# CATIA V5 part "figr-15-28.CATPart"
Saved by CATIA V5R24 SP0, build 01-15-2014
Part number: Part1
Bounding box of the stored display mesh (mm): x -61.282 to 61.282, y -26.72 to 26.72, z 0 to 45.75
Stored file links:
  D:\KAVITA\CATIA V5-6R2014 Project_ Kavita\CATIA V5-6R2014_partfiles\Partfiles\c15_catia_v5-6r2014_prt\figr-15-28.CATPart
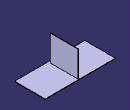
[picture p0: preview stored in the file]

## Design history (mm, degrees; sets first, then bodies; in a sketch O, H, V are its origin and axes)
SheetMetalParameters1: Thickness 0.75, BendRadius 1, KFactor 0.356492 {= log(min(100,max(20*SheetMetalParameters1.BendRadius,SheetMetalParameters1.Thickness)/SheetMetalParameters1.Thickness))/log(100)/2}, ReliefRadialLength 1, ReliefAxialLength 2, MinimumBendRadius 0
Body1 (main body)
  Sketch1 on xy-plane, origin (0, 0, 0), H (1, 0, 0), V (0, 1, 0)
    line L1 (61.282, 26.7197) -> (61.282, -26.7197)
    line L2 (61.282, -26.7197) -> (-61.282, -26.7197)
    line L3 (-61.282, -26.7197) -> (-61.282, 26.7197)
    line L4 (-61.282, 26.7197) -> (61.282, 26.7197)
    vertical: L1 V, L3 V
    horizontal: L2 H, L4 H
    equidistance: L1 L3 O, L2 L4 O
  Wall1: Thickness 0.75, Profile Sketch1
  Sketch2 on face of Wall1, origin (0, 0, 0.75), H (1, 0, 0), V (0, 1, 0)
    line L1 (1.9015, 25.4615) -> (1.9015, -22.9675)
    vertical: L1 V
  d_Extrude1: Extrude_Thickness 0.75, Extrude_Profile Sketch2, Extrude_StartLength 45, Extrude_EndLength 0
